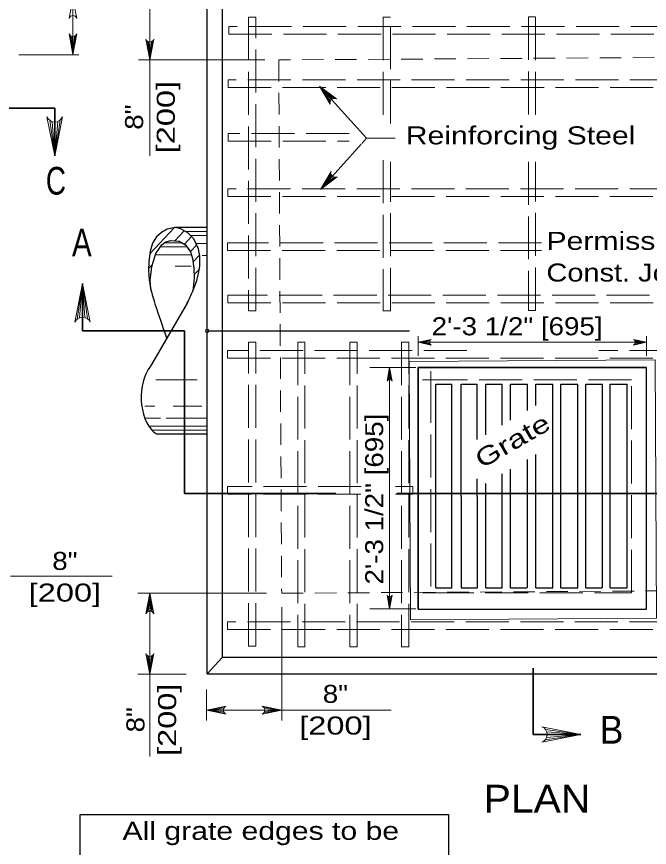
# Model space of a CAD drawing. Extents: x 1329.9 to 1363.9, y 715.5 to 737.5.
# Drawn here: x 1346.18 to 1351.66, y 726.62 to 733.81 of the extents above; entities that cross this region are included whole.
import ezdxf
from ezdxf.enums import TextEntityAlignment as Align

# ---------------------------------------------------------------- set-up
doc = ezdxf.new("R2010")
doc.units = 0
doc.header["$LTSCALE"] = 0.062
doc.header["$PDMODE"] = 32
doc.header["$PDSIZE"] = 0.031
doc.linetypes.add('LONG_DASHED', pattern=[7.5, 6, -1.5])
doc.linetypes.add('MEDIUM_DASHED', pattern=[4.5, 3, -1.5])
doc.layers.add('1', color=7, linetype='Continuous', lineweight=13)

msp = doc.modelspace()

# ---------------------------------------------------------------- linework, layer by layer
at = {"layer": '1'}
for p, q in [((1346.67067, 733.48308), (1346.67067, 734.72233)), ((1347.3355, 732.60442), (1347.3355, 734.10725)), ((1346.67067, 733.67733), (1346.67067, 733.97267)), ((1346.67067, 733.48308), (1346.67067, 733.67733)), ((1346.64933, 733.64433), (1346.67067, 733.48308)), ((1346.65992, 733.63892), (1346.67067, 733.48308)), ((1346.69417, 733.64625), (1346.67067, 733.48308)), ((1346.68433, 733.64008), (1346.67067, 733.48308)), ((1346.67067, 733.63725), (1346.67067, 733.48308)), ((1347.31417, 733.59617), (1347.3355, 733.435)), ((1347.32475, 733.59075), (1347.3355, 733.435)), ((1347.35908, 733.59808), (1347.3355, 733.435)), ((1347.34917, 733.59192), (1347.3355, 733.435)), ((1347.3355, 733.58908), (1347.3355, 733.435)), ((1346.20225, 733.47808), (1346.72133, 733.47808)), ((1347.23817, 733.435), (1348.33042, 733.435)), ((1348.90642, 733.09275), (1348.80392, 733.20658)), ((1348.89758, 733.081), (1348.80392, 733.20658)), ((1348.894, 733.0695), (1348.80392, 733.20658)), ((1348.91592, 733.09908), (1348.80392, 733.20658)), ((1348.92783, 733.10242), (1348.80392, 733.20658)), ((1346.471, 732.91075), (1346.51367, 732.60617)), ((1346.49208, 732.9005), (1346.51367, 732.60617)), ((1346.56075, 732.91433), (1346.51367, 732.60617)), ((1346.541, 732.90267), (1346.51367, 732.60617)), ((1346.51367, 732.89733), (1346.51367, 732.60617)), ((1349.20833, 732.75708), (1349.16733, 732.71142)), ((1349.16192, 732.70533), (1348.81142, 732.31458)), ((1348.90175, 732.44892), (1348.81142, 732.31458)), ((1348.90642, 732.43742), (1348.81142, 732.31458)), ((1348.91375, 732.42867), (1348.81142, 732.31458)), ((1348.92633, 732.42117), (1348.81142, 732.31458)), ((1348.93817, 732.41875), (1348.81142, 732.31458)), ((1347.5465, 731.98167), (1347.3345, 731.75742)), ((1347.63325, 731.95633), (1347.55075, 731.869)), ((1347.69717, 731.90625), (1347.63467, 731.84025)), ((1347.83075, 731.94892), (1347.64658, 731.94892)), ((1347.83075, 731.91433), (1347.68908, 731.91433)), ((1347.6575, 731.81717), (1347.42675, 731.81717)), ((1347.61467, 731.85175), (1347.4605, 731.85175)), ((1347.741, 731.83542), (1347.68592, 731.77708)), ((1347.83075, 731.84508), (1347.73658, 731.84508)), ((1347.69525, 731.748), (1347.3845, 731.748)), ((1347.76625, 731.74475), (1347.70858, 731.68358)), ((1347.83075, 731.74133), (1347.78883, 731.74133)), ((1347.35892, 731.66567), (1347.32458, 731.62933)), ((1347.69308, 731.64992), (1347.55608, 731.64992)), ((1347.76367, 731.62458), (1347.71717, 731.57525)), ((1347.34, 731.52842), (1347.33125, 731.51908)), ((1347.33983, 731.52475), (1347.33183, 731.51617)), ((1347.71767, 731.54892), (1347.70683, 731.435)), ((1347.70683, 731.435), (1347.74067, 731.5265)), ((1346.70642, 731.19317), (1346.7535, 731.50142)), ((1346.72608, 731.20483), (1346.7535, 731.50142)), ((1346.7535, 731.21025), (1346.7535, 731.50142)), ((1346.775, 731.20708), (1346.7535, 731.50142)), ((1346.79608, 731.19675), (1346.7535, 731.50142)), ((1347.34242, 731.47858), (1347.33917, 731.47517)), ((1347.714, 731.4545), (1347.70817, 731.44817)), ((1347.70858, 731.43983), (1347.70708, 731.43833)), ((1349.65717, 730.8755), (1349.65717, 731.04342)), ((1351.62975, 730.8755), (1351.62975, 731.04342)), ((1349.75875, 731.00675), (1349.65717, 730.99167)), ((1349.75525, 730.99933), (1349.65717, 730.99167)), ((1349.65717, 730.99167), (1351.62975, 730.99167)), ((1349.75425, 730.99167), (1349.65717, 730.99167)), ((1349.756, 730.98208), (1349.65717, 730.99167)), ((1349.75992, 730.97508), (1349.65717, 730.99167)), ((1351.52708, 731.00833), (1351.62975, 730.99167)), ((1351.52825, 730.97667), (1351.62975, 730.99167)), ((1351.53092, 731.00133), (1351.62975, 730.99167)), ((1351.53167, 730.98408), (1351.62975, 730.99167)), ((1351.53275, 730.99167), (1351.62975, 730.99167)), ((1349.23825, 730.77408), (1349.63508, 730.77408)), ((1349.39325, 730.66533), (1349.40892, 730.77408)), ((1349.39983, 730.6695), (1349.40892, 730.77408)), ((1349.40892, 730.67133), (1349.40892, 730.77408)), ((1349.41608, 730.67025), (1349.40892, 730.77408)), ((1349.42317, 730.66658), (1349.40892, 730.77408)), ((1347.38725, 730.66658), (1347.74492, 730.66708)), ((1347.38025, 730.43917), (1347.29192, 730.43917)), ((1347.78617, 730.43917), (1347.537, 730.43917)), ((1347.42908, 730.33525), (1347.29192, 730.33525)), ((1347.83075, 730.33525), (1347.47792, 730.33525)), ((1347.83075, 730.266), (1347.32625, 730.266)), ((1347.83075, 730.2315), (1347.35433, 730.2315)), ((1349.61058, 729.74258), (1349.61058, 729.67625)), ((1347.01083, 728.96908), (1346.13208, 728.96908)), ((1347.23283, 728.82033), (1348.34375, 728.82033)), ((1347.31192, 728.65725), (1347.3355, 728.82033)), ((1347.32183, 728.66342), (1347.3355, 728.82033)), ((1347.3355, 727.40742), (1347.3355, 728.82033)), ((1347.3355, 728.66625), (1347.3355, 728.82033)), ((1347.34625, 728.66458), (1347.3355, 728.82033)), ((1347.35683, 728.65908), (1347.3355, 728.82033)), ((1349.39475, 728.79375), (1349.40892, 728.68625)), ((1349.40175, 728.79008), (1349.40892, 728.68625)), ((1349.42467, 728.795), (1349.40892, 728.68625)), ((1349.41808, 728.79092), (1349.40892, 728.68625)), ((1349.40892, 728.789), (1349.40892, 728.68625)), ((1349.23825, 728.68625), (1349.63508, 728.68625)), ((1347.31417, 728.28142), (1347.3355, 728.12017)), ((1347.32475, 728.27592), (1347.3355, 728.12017)), ((1347.35908, 728.28325), (1347.3355, 728.12017)), ((1347.34917, 728.27708), (1347.3355, 728.12017)), ((1347.3355, 728.27425), (1347.3355, 728.12017)), ((1347.23283, 728.12017), (1347.64908, 728.12017)), ((1347.82642, 727.98617), (1347.82642, 727.71833)), ((1347.97875, 727.83142), (1347.82642, 727.80883)), ((1347.97358, 727.82025), (1347.82642, 727.80883)), ((1347.972, 727.80883), (1347.82642, 727.80883)), ((1347.97467, 727.79442), (1347.82642, 727.80883)), ((1347.9805, 727.78392), (1347.82642, 727.80883)), ((1347.82642, 727.80883), (1349.42308, 727.80883)), ((1348.3215, 727.83383), (1348.47558, 727.80883)), ((1348.32333, 727.78633), (1348.47558, 727.80883)), ((1348.32733, 727.82333), (1348.47558, 727.80883)), ((1348.3285, 727.7975), (1348.47558, 727.80883)), ((1348.33008, 727.80883), (1348.47558, 727.80883)), ((1350.75792, 727.641), (1351.06258, 727.59833)), ((1350.75433, 727.55125), (1351.06258, 727.59833)), ((1350.766, 727.571), (1351.06258, 727.59833)), ((1350.76825, 727.61992), (1351.06258, 727.59833)), ((1350.77142, 727.59833), (1351.06258, 727.59833))]:
    msp.add_line(p, q, dxfattribs=at)
at = {"layer": '1', "lineweight": 25}
for p, q in [((1347.83075, 728.1235), (1347.83075, 734.1075)), ((1347.96533, 728.26592), (1347.96533, 733.96508)), ((1347.83075, 731.9835), (1347.5555, 731.9835)), ((1347.71625, 731.63392), (1347.71767, 731.54892)), ((1347.74067, 731.5265), (1347.75742, 731.58625)), ((1347.6595, 731.32925), (1347.34925, 730.79858)), ((1347.832, 731.09017), (1349.58217, 731.09017)), ((1349.65717, 730.77408), (1351.62975, 730.77408)), ((1349.65717, 728.68233), (1349.65717, 730.77408)), ((1351.62975, 728.68233), (1351.62975, 730.77408)), ((1349.80775, 728.86783), (1349.80775, 730.63017)), ((1349.80775, 730.63017), (1349.94742, 730.63017)), ((1349.94742, 730.44033), (1349.94742, 730.63017)), ((1350.02625, 730.63017), (1350.16592, 730.63017)), ((1350.02625, 730.50908), (1350.02625, 730.63017)), ((1350.16658, 730.50908), (1350.16658, 730.63017)), ((1350.16658, 730.14967), (1350.16658, 730.6115)), ((1350.24, 730.63017), (1350.38333, 730.63017)), ((1350.24, 730.50908), (1350.24, 730.63017)), ((1350.24, 730.19217), (1350.24, 730.61117)), ((1350.38333, 730.50908), (1350.38333, 730.63017)), ((1350.4555, 730.63017), (1350.60008, 730.63017)), ((1350.4555, 730.50908), (1350.4555, 730.63017)), ((1350.60008, 730.44033), (1350.60008, 730.63017)), ((1350.60008, 730.40083), (1350.60008, 730.63017)), ((1350.67467, 730.63017), (1350.82033, 730.63017)), ((1350.67467, 730.44408), (1350.67467, 730.63017)), ((1350.67467, 730.44408), (1350.67467, 730.63017)), ((1350.88892, 730.63017), (1351.03525, 730.63017)), ((1350.88892, 729.02567), (1350.88892, 730.63017)), ((1351.03525, 729.02567), (1351.03525, 730.63017)), ((1351.10567, 730.63017), (1351.25083, 730.63017)), ((1351.10567, 729.02567), (1351.10567, 730.63017)), ((1351.25083, 729.02567), (1351.25083, 730.63017)), ((1351.31708, 730.63017), (1351.46208, 730.63017)), ((1351.31708, 729.02567), (1351.31708, 730.63017)), ((1351.46208, 728.86783), (1351.46208, 730.63017)), ((1349.94742, 729.65833), (1349.94742, 730.52717)), ((1350.02625, 730.06833), (1350.02625, 730.52717)), ((1350.38333, 730.27525), (1350.38333, 730.50908)), ((1350.4555, 730.31708), (1350.4555, 730.50908)), ((1347.83075, 730.19692), (1347.39325, 730.19692)), ((1350.02625, 729.65833), (1350.02625, 730.06433)), ((1350.67467, 729.02567), (1350.67467, 730.02125)), ((1350.60008, 728.86783), (1350.60008, 729.97825)), ((1350.4555, 728.86783), (1350.4555, 729.89475)), ((1350.16658, 729.65833), (1350.16658, 729.80942)), ((1350.38333, 728.86783), (1350.38333, 729.85308)), ((1350.24, 729.65833), (1350.24, 729.77033)), ((1349.94742, 728.86783), (1349.94742, 729.65833)), ((1350.02625, 729.65833), (1350.02625, 728.86783)), ((1350.16658, 729.65833), (1350.16658, 728.86783)), ((1350.24, 728.86783), (1350.24, 729.65833)), ((1350.88892, 728.86783), (1350.88892, 729.18325)), ((1351.03525, 728.86783), (1351.03525, 729.18325)), ((1351.31708, 728.86783), (1351.31708, 729.18325)), ((1350.67467, 728.86783), (1350.67467, 729.07742)), ((1350.82033, 728.86783), (1350.82033, 729.05583)), ((1351.10567, 728.86783), (1351.10567, 729.04633)), ((1351.25083, 728.86783), (1351.25083, 729.06058)), ((1349.80775, 728.86783), (1349.94742, 728.86783)), ((1350.02625, 728.86783), (1350.16592, 728.86783)), ((1350.24, 728.86783), (1350.38333, 728.86783)), ((1350.4555, 728.86783), (1350.59517, 728.86783)), ((1350.67467, 728.86783), (1350.82033, 728.86783)), ((1350.88892, 728.86783), (1351.03525, 728.86783)), ((1351.10567, 728.86783), (1351.24533, 728.86783)), ((1351.31708, 728.86783), (1351.46208, 728.86783)), ((1349.65717, 728.68233), (1351.62975, 728.68233)), ((1347.96533, 728.26592), (1347.83075, 728.1235)), ((1347.96533, 728.26592), (1353.34842, 728.26592)), ((1347.83075, 728.1235), (1353.483, 728.1235))]:
    msp.add_line(p, q, dxfattribs=at)
at = {"layer": '1', "linetype": 'LONG_DASHED'}
for p, q in [((1349.41725, 733.80392), (1349.35458, 733.80392)), ((1349.35458, 733.80392), (1349.35458, 732.90458)), ((1349.41725, 732.8835), (1349.41725, 733.80392)), ((1350.67158, 733.80642), (1350.60892, 733.80642)), ((1350.60892, 733.80642), (1350.60892, 732.94675)), ((1350.67158, 732.96075), (1350.67158, 733.80642)), ((1348.01383, 732.79808), (1348.01383, 732.73175)), ((1349.05858, 732.79808), (1348.01383, 732.79808)), ((1348.01383, 732.73175), (1349.05858, 732.73175)), ((1349.35458, 732.56742), (1349.35458, 731.26392)), ((1349.41725, 731.26392), (1349.41725, 732.55342)), ((1350.60892, 732.55342), (1350.60892, 731.26642)), ((1350.67158, 731.26642), (1350.67158, 732.55342)), ((1348.00742, 731.85117), (1348.00742, 731.78483)), ((1350.72117, 731.85117), (1348.00742, 731.85117)), ((1348.00742, 731.78483), (1350.72117, 731.78483)), ((1348.011, 731.39942), (1348.011, 731.33308)), ((1352.12917, 731.39942), (1348.011, 731.39942)), ((1348.011, 731.33308), (1352.12917, 731.33308)), ((1349.35458, 731.26392), (1349.41725, 731.26392)), ((1350.60892, 731.26642), (1350.67158, 731.26642)), ((1348.18833, 728.36258), (1348.18833, 730.99317)), ((1348.18833, 730.99317), (1348.25092, 730.99317)), ((1348.25092, 728.36258), (1348.25092, 730.99317)), ((1348.67658, 730.99317), (1348.61392, 730.99317)), ((1348.61392, 730.99317), (1348.61392, 728.35742)), ((1348.67658, 728.35742), (1348.67658, 730.99317)), ((1349.12842, 730.99317), (1349.06575, 730.99317)), ((1349.06575, 730.99317), (1349.06575, 728.35742)), ((1349.12842, 728.35742), (1349.12842, 730.99317)), ((1349.57558, 730.99317), (1349.51292, 730.99317)), ((1349.51292, 730.99317), (1349.51292, 728.35742)), ((1349.57558, 728.35742), (1349.57558, 730.99317)), ((1348.00833, 730.91975), (1348.00833, 730.85342)), ((1350.07617, 730.91975), (1348.00833, 730.91975)), ((1353.27142, 730.91975), (1351.21892, 730.91975)), ((1349.76408, 730.66608), (1349.76408, 730.74058)), ((1349.76408, 730.66608), (1349.69375, 730.66608)), ((1348.00833, 729.74258), (1348.00833, 729.67625)), ((1349.16333, 729.74258), (1348.00833, 729.74258)), ((1349.61058, 729.74258), (1349.459, 729.74258)), ((1349.15925, 729.67625), (1348.00833, 729.67625)), ((1349.61058, 729.67625), (1349.459, 729.67625)), ((1349.76408, 728.82458), (1349.69375, 728.82458)), ((1348.18833, 728.36258), (1348.25092, 728.36258)), ((1348.61392, 728.35742), (1348.67658, 728.35742)), ((1349.06575, 728.35742), (1349.12842, 728.35742)), ((1349.51292, 728.35742), (1349.57558, 728.35742))]:
    msp.add_line(p, q, dxfattribs=at)
at = {"layer": '1', "lineweight": 35}
for p, q in [((1346.7535, 731.50142), (1346.7535, 731.09017)), ((1346.7535, 731.09017), (1347.634, 731.09017)), ((1347.634, 729.68367), (1347.634, 731.09017)), ((1347.634, 729.68367), (1348.94375, 729.68367)), ((1349.47242, 729.68367), (1351.81367, 729.68367)), ((1350.65133, 727.59833), (1350.65133, 728.17325)), ((1351.06258, 727.59833), (1350.65133, 727.59833))]:
    msp.add_line(p, q, dxfattribs=at)
at = {"layer": '1', "linetype": 'MEDIUM_DASHED'}
msp.add_line((1348.47683, 728.82033), (1352.86742, 728.84767), dxfattribs=at)
at = {"layer": '1'}
for points in [[(1346.637, 733.79458), (1346.67067, 733.97267), (1346.70433, 733.79458)], [(1346.70433, 733.66125), (1346.67067, 733.48308), (1346.637, 733.66125)], [(1347.36917, 733.61308), (1347.3355, 733.435), (1347.30183, 733.61308)], [(1348.896, 733.05133), (1348.80392, 733.20658), (1348.94867, 733.09867)], [(1349.45775, 732.75708), (1349.20833, 732.75708), (1348.80392, 733.20658)], [(1346.58092, 732.94267), (1346.51367, 732.60617), (1346.44633, 732.94267)], [(1348.956, 732.42275), (1348.81142, 732.31458), (1348.90325, 732.47008)], [(1347.75742, 731.58625), (1347.76808, 731.65033), (1347.76767, 731.73608), (1347.75683, 731.80133), (1347.7175, 731.88633), (1347.664, 731.93925), (1347.60417, 731.9725), (1347.5555, 731.9835), (1347.48583, 731.97008), (1347.43775, 731.94175), (1347.39325, 731.90325), (1347.35967, 731.84892), (1347.33742, 731.78067), (1347.32625, 731.69183), (1347.32392, 731.61242), (1347.32917, 731.53083), (1347.34417, 731.44883)], [(1347.34417, 731.44883), (1347.33983, 731.52617), (1347.34625, 731.59475), (1347.35383, 731.64725), (1347.36658, 731.69442), (1347.38817, 731.759), (1347.41233, 731.79817), (1347.43775, 731.83183), (1347.46842, 731.85867), (1347.51417, 731.87225), (1347.59042, 731.86542), (1347.64517, 731.8345), (1347.68833, 731.77392), (1347.70358, 731.71608), (1347.71625, 731.63392)], [(1346.68617, 731.16492), (1346.7535, 731.50142), (1346.82075, 731.16492)], [(1349.76933, 730.968), (1349.65717, 730.99167), (1349.76933, 731.01542)], [(1351.51767, 731.01542), (1351.62975, 730.99167), (1351.51767, 730.968)], [(1349.3865, 730.65542), (1349.40892, 730.77408), (1349.43133, 730.65542)], [(1349.40892, 728.68625), (1349.40892, 729.47217), (1349.40892, 730.77408)], [(1347.30183, 728.64225), (1347.3355, 728.82033), (1347.36917, 728.64225)], [(1349.43133, 728.805), (1349.40892, 728.68625), (1349.3865, 728.805)], [(1348.47558, 728.699), (1348.47558, 728.29458), (1348.47558, 727.71833)], [(1347.36917, 728.29825), (1347.3355, 728.12017), (1347.30183, 728.29825)], [(1347.99467, 727.77325), (1347.82642, 727.80883), (1347.99467, 727.8445)], [(1348.30742, 727.8445), (1348.47558, 727.80883), (1348.30742, 727.77325)], [(1350.72608, 727.53108), (1351.06258, 727.59833), (1350.72608, 727.66567)]]:
    msp.add_lwpolyline(points, dxfattribs=at)
at = {"layer": '1', "linetype": 'LONG_DASHED'}
for points in [[(1348.18833, 733.80392), (1348.18833, 731.26392), (1348.25092, 731.26392), (1348.25092, 733.80392)], [(1348.01858, 733.65842), (1353.28167, 733.65842), (1353.28167, 733.72475), (1348.01858, 733.72475)], [(1348.01208, 733.19508), (1353.27517, 733.19508), (1353.27517, 733.26133), (1348.01208, 733.26133)], [(1348.01017, 732.254), (1353.27325, 732.254), (1353.27325, 732.32033), (1348.01017, 732.32033)], [(1351.49975, 728.82458), (1351.49975, 730.66608), (1349.76408, 730.66608), (1349.76408, 728.82458)], [(1348.00833, 728.50783), (1353.27142, 728.50783), (1353.27142, 728.57417), (1348.00833, 728.57417)]]:
    msp.add_lwpolyline(points, close=True, dxfattribs=at)
at = {"layer": '1', "linetype": 'MEDIUM_DASHED'}
msp.add_lwpolyline([(1352.86742, 728.84767), (1352.84175, 733.46225), (1348.45, 733.435), (1348.47558, 728.82033)], dxfattribs=at)
at = {"layer": '1', "lineweight": 35}
msp.add_lwpolyline([(1340.12008, 733.01742), (1346.51367, 733.01742), (1346.51367, 732.60617)], dxfattribs=at)
at = {"layer": '1', "lineweight": 25}
for points in [[(1347.70683, 731.435), (1347.74067, 731.5265), (1347.75742, 731.58625), (1347.76808, 731.65033), (1347.76767, 731.73608), (1347.75683, 731.80133), (1347.7175, 731.88633), (1347.664, 731.93925), (1347.60417, 731.9725), (1347.5555, 731.9835), (1347.48583, 731.97008), (1347.43775, 731.94175), (1347.39325, 731.90325), (1347.35967, 731.84892), (1347.33742, 731.78067), (1347.32625, 731.69183), (1347.32392, 731.61242), (1347.32917, 731.53083), (1347.34417, 731.44883)], [(1347.34417, 731.44883), (1347.33983, 731.52617), (1347.34625, 731.59475), (1347.35383, 731.64725), (1347.36658, 731.69442), (1347.38817, 731.759), (1347.41233, 731.79817), (1347.43775, 731.83183), (1347.46842, 731.85867), (1347.51417, 731.87225), (1347.59042, 731.86542), (1347.64517, 731.8345), (1347.68833, 731.77392), (1347.70358, 731.71608), (1347.71625, 731.63392), (1347.71767, 731.54892), (1347.70683, 731.435)], [(1350.82033, 729.02567), (1350.82033, 730.15017), (1350.82033, 730.63017)]]:
    msp.add_lwpolyline(points, dxfattribs=at)
at = {"layer": '1', "linetype": 'LONG_DASHED'}
msp.add_lwpolyline([(1348.00833, 730.85342), (1353.27142, 730.85342), (1353.27142, 730.91975)], dxfattribs=at)
at = {"layer": '1'}
msp.add_lwpolyline([(1349.59067, 728.591), (1349.57825, 730.82658), (1351.70533, 730.83983), (1351.71775, 728.60417)], close=True, dxfattribs=at)
at = {"layer": '1', "lineweight": 25}
for points in [[(1349.65717, 730.77408), (1349.65717, 728.68233), (1351.62975, 728.68233), (1351.62975, 730.77408)], [(1346.73325, 726.90575), (1349.91742, 726.90575), (1349.91742, 726.33358), (1346.73325, 726.33358)]]:
    msp.add_lwpolyline(points, close=True, dxfattribs=at)
at = {"layer": '1'}
for centre, radius, start, end in [((1348.93195, 733.06438), 0.03822, 64.06448, 199.8906), ((1346.51358, 732.9698), 0.07261, 202.08782, 337.91395), ((1348.93917, 732.45707), 0.03822, 160.19494, 296.02106), ((1346.75356, 731.13777), 0.07261, 22.08782, 157.91395), ((1350.69893, 727.59844), 0.07261, 292.08605, 67.91218)]:
    msp.add_arc(centre, radius, start, end, dxfattribs=at)
for centre, major_axis, start_param, end_param in [((1346.67066, 733.78014), (0, 0.03844), 5.0978942, 7.4685073), ((1346.67065, 733.67567), (0, -0.03844), 5.0978942, 7.4685073), ((1347.3355, 733.62751), (0, -0.03844), 5.0978942, 7.4685073), ((1349.77844, 730.99171), (0, 0.02563), 0.3855052, 2.7561184), ((1351.50853, 730.99171), (0, -0.02563), 0.3855052, 2.7561184), ((1349.40893, 730.64574), (0, 0.02563), 5.0978942, 7.4685073), ((1349.40893, 728.81463), (0, -0.02563), 5.0978942, 7.4685073), ((1347.3355, 728.6278), (0, 0.03844), 5.0978942, 7.4685073), ((1347.3355, 728.3127), (0, -0.03844), 5.0978942, 7.4685073), ((1348.00831, 727.80886), (0, 0.03844), 0.3855052, 2.7561184), ((1348.29374, 727.80886), (0, -0.03844), 0.3855052, 2.7561184)]:
    msp.add_ellipse(centre, major_axis=major_axis, ratio=0.944544, start_param=start_param, end_param=end_param, dxfattribs=at)
at = {"layer": '1', "lineweight": 25}
for centre, major_axis, start_param, end_param in [((1347.6858, 730.52339), (0, 0.45022), 0.9130573, 1.3757934), ((1347.73069, 730.51562), (0, 0.49831), 1.3789738, 2.0303511), ((1347.5555, 730.44357), (0, -0.30064), 5.2308377, 5.6746503)]:
    msp.add_ellipse(centre, major_axis=major_axis, ratio=0.944544, start_param=start_param, end_param=end_param, dxfattribs=at)
for points in [[(1347.34417, 731.44883), (1347.3615, 731.37742), (1347.39808, 731.263), (1347.48092, 731.03008)], [(1347.6595, 731.32925), (1347.67808, 731.36808), (1347.69367, 731.40333), (1347.70683, 731.435)]]:
    msp.add_open_spline(points, degree=3, dxfattribs=at)
at = {"layer": '1'}
msp.add_point((1347.83075, 731.09017), dxfattribs=at)

# ---------------------------------------------------------------- texts
for s, rotation, width, p in [('[200]', 90, 1.35, (1347.55158, 732.93975)), ('8"', 90, 1.15, (1347.2775, 732.93975)), ('Grate', 30, 1.35, (1350.51021, 730.0713)), ('[200]', 90, 1.35, (1347.56308, 727.72575)), ('8"', 90, 1.15, (1347.289, 727.72575))]:
    msp.add_text(s, height=0.156, rotation=rotation, dxfattribs=dict(at, width=width)).set_placement(p, align=Align.CENTER)
for s, height, width, p in [('Reinforcing Steel', 0.156, 1.25, (1349.5485, 732.70392)), ('Permissible', 0.156, 1.25, (1350.76508, 731.79125)), ('Const. Joint', 0.156, 1.2, (1350.76508, 731.51717)), ('2\'-3 1/2" [695]', 0.156, 1.15, (1349.77242, 731.05217)), ('PLAN', 0.24, 1.1, (1350.22225, 726.92317))]:
    msp.add_text(s, height=height, dxfattribs=dict(at, width=width)).set_placement(p)
for s, height, width, p in [('C', 0.24, 0.75, (1346.52358, 732.26925)), ('A', 0.24, 0.8, (1346.74758, 731.73417)), ('8"', 0.156, 1.15, (1346.60117, 729.022)), ('[200]', 0.156, 1.35, (1346.60117, 728.74792)), ('8"', 0.156, 1.15, (1348.94025, 727.87183)), ('[200]', 0.156, 1.35, (1348.94025, 727.59775)), ('B', 0.24, 0.95, (1351.32825, 727.51875)), ('All grate edges to be', 0.156, 1.25, (1348.29508, 726.68675))]:
    msp.add_text(s, height=height, dxfattribs=dict(at, width=width)).set_placement(p, align=Align.CENTER)
at = {"layer": '1', "width": 1.15}
msp.add_text('2\'-3 1/2" [695]', height=0.156, rotation=90, dxfattribs=at).set_placement((1349.35367, 728.89608))

doc.saveas('drawing.dxf')
